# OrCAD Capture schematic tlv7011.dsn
size A
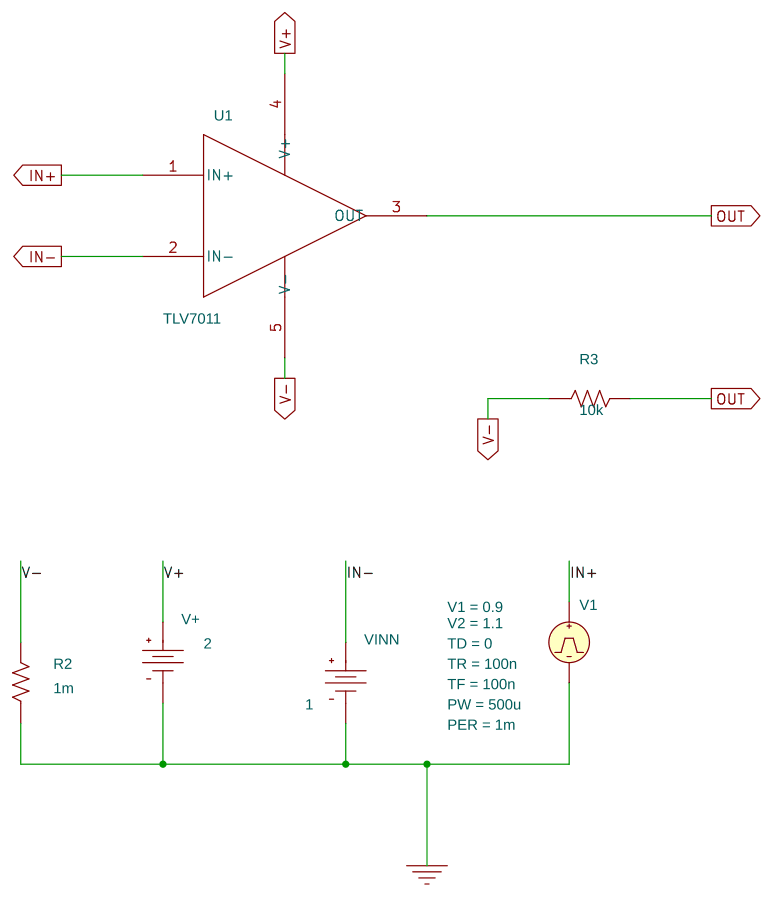
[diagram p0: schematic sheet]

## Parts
R2  1m  [AXRC05]
R3  10k  [AXRC05]
U1  TLV7011
V1  VPULSE
V+  VDC
VINN  VDC

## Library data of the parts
R2 R3 = R
U1 = TLV7011_1
V1 = VPULSE: PER: 1m; PW: 500u; TD: 0; TF: 100n; TR: 100n; V1: 0.9; V2: 1.1
V+ = VDC: DC: 2
VINN = VDC: DC: 1

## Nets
0: R2.1 V1.2(-) V+.1(-) VINN.1(-)
IN+: U1.1(IN+) V1.1(+)
IN-: U1.2(IN-) VINN.0(+)
OUT: R3.2 U1.3(OUT)
V+: U1.4(V+) V+.0(+)
V-: R2.2 R3.1 U1.5(V-)
